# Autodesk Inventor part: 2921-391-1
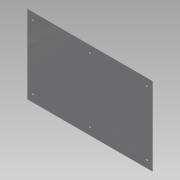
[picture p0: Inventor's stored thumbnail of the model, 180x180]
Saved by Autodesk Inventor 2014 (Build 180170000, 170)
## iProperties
Company: NHTSA/VRTC
Created: 2012-02
Part Number: 2921-391-1
Project: CHILD SIDE IMPACT SLED
Material: Steel, Mild
Description: SEAT BACK CUSHION MTG. PLATE
Document SubType Name: Modeling
Designer: Mike Vanvoorhis
Mass: 3776.43 g
Surface Area: 4772.79 cm^2
Volume: 480.462 cm^3
Density: 7.86 g/cm^3
Appearance: Steel
Stock Number: PL 14 Ga. x 385.0 (15 3/16") x 587.5 (23 1/8")
Title: Seat Back Cushoion Mtg. Plate
Subject: Child Side Impact Sled
Author: Dave Walker
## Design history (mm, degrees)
sketch "Sketch1"
  geometry: L1 (-307.5, 192.5)-(307.5, 192.5); L2 (307.5, 192.5)-(307.5, -192.5); L3 (307.5, -192.5)-(-307.5, -192.5); L4 (-307.5, -192.5)-(-307.5, 192.5); L5 (0, 269.5)-(0, -269.5) reference; L6 (-430.5, 0)-(430.5, 0) reference
  constraints: 8 end point, 2 parallel, 1 horizontal, 1 perpendicular, 2 other
  dimensions: "d0" = 615 distance of L1.start L1.end; "d1" = 385 distance of L3.end L1.start
extrude "Extrusion1" new body sketch "Sketch1" distance "d2" = 2.032; taper "d3" = 0 deg
sketch "Sketch2"
  geometry: L1 (307.5, -192.5)-(-307.5, -192.5) reference; L2 (-307.5, -192.5)-(-307.5, 192.5) reference; 3 further points
  constraints: 1 vertical alignment
  dimensions: "d4" = 35 distance from line of point (-280, -157.5) L1; "d7" = 27.5 distance from line of point (-280, -157.5) L2; "d15" = 350 distance from line of point (-280, 157.5) L1
hole "Hole1" sketch "Sketch2" at (-280, -157.5), (-280, 157.5) diameter "d8" = 8.3312; stored, may be unused: countersink angle "d12" = 90 deg, drill point angle "d14" = 118 deg; dims "d9" = 6, "d10" = 4, "d11" = 2, "d13" = 8
mirror "Mirror1"
sketch "Sketch3"
  geometry: C1 r 4.166 at (-280, 157.5) reference; C2 r 4.166 at (-280, -157.5) reference; 3 further points
  constraints: 2 horizontal alignment, 2 vertical alignment
hole "Hole2" sketch "Sketch3" at (0, -157.5), (0, 157.5) diameter "d17" = 8.3312; stored, may be unused: countersink angle "d21" = 90 deg, drill point angle "d23" = 118 deg; dims "d18" = 6, "d19" = 4, "d20" = 2, "d22" = 8
body "Solid1"
